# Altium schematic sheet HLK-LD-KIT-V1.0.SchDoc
size A4
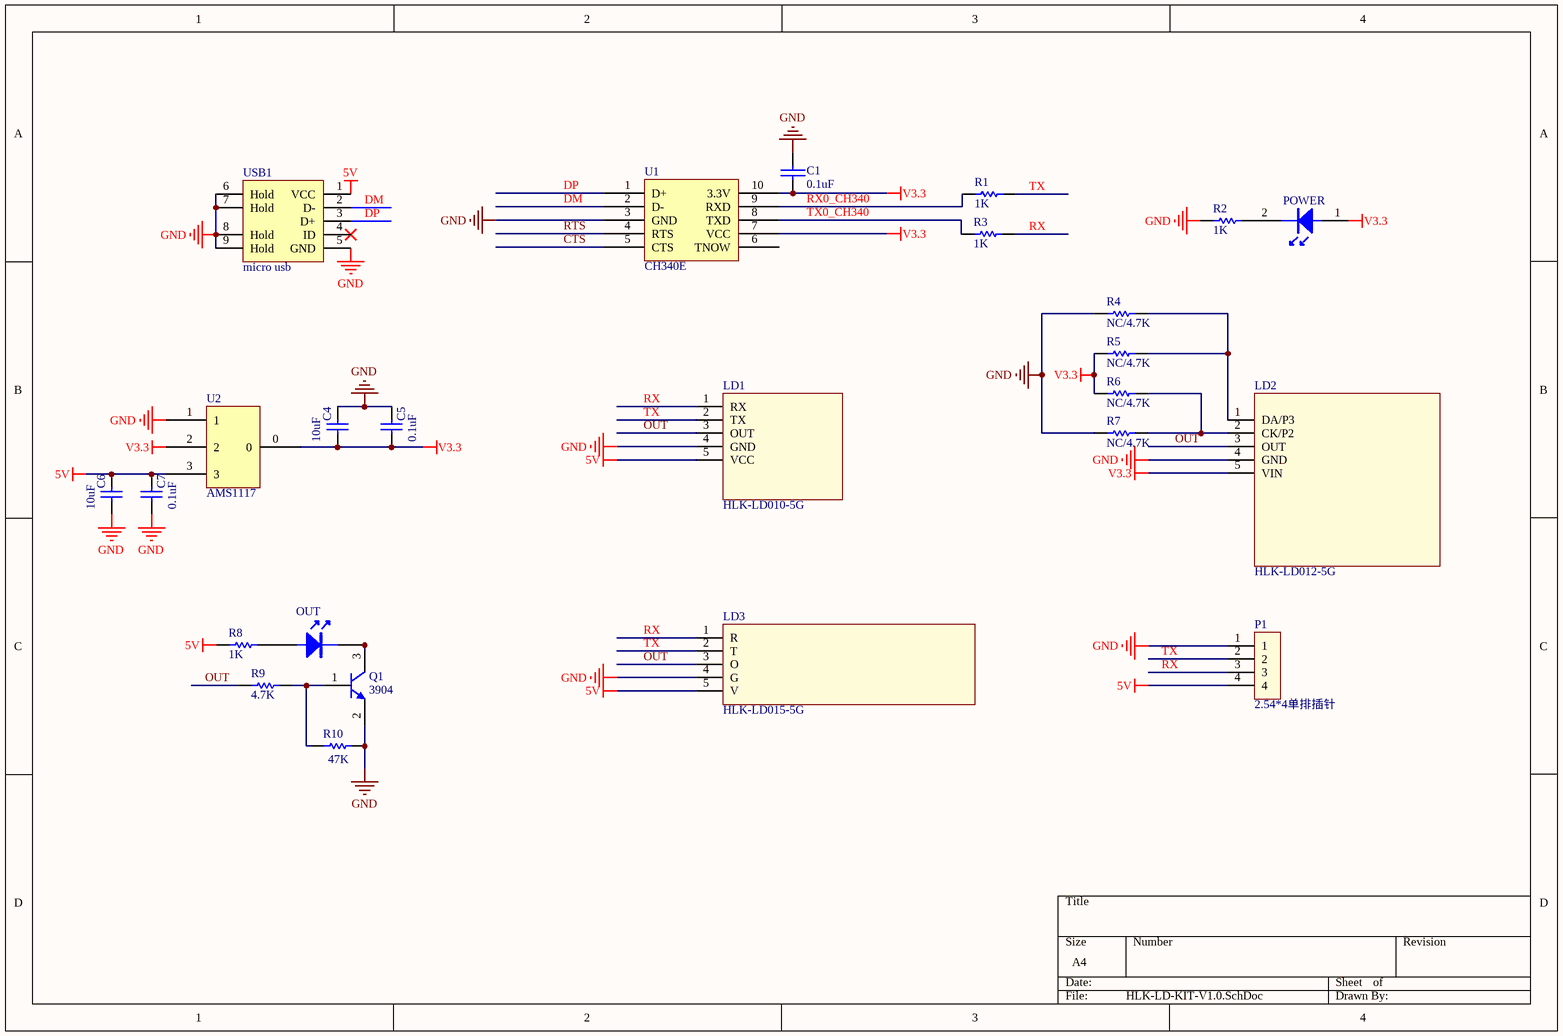
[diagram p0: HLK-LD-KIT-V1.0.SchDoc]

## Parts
C1  0.1uF  [0603]
C4  10uF  [0603]
C5  0.1uF  [0603]
C6  10uF  [0603]
C7  0.1uF  [0603]
LD1  HLK-LD010-5G  [HLK-LD010-5G]
LD2  HLK-LD012-5G  [HLK-LD012-5G]
LD3  HLK-LD015-5G  [HLK-LD015-5G]
OUT  (no value)  [0603LED]
P1  2.54*4单排插针  [SIP_4P_2.54]
POWER  LED  [0603LED]  (value not drawn)
Q1  3904  [SOT-23]
R1  1K  [0603]
R2  1K  [0603]
R3  1K  [0603]
R4  NC/4.7K  [0603]
R5  NC/4.7K  [0603]
R6  NC/4.7K  [0603]
R7  NC/4.7K  [0603]
R8  1K  [0603]
R9  4.7K  [0603]
R10  47K  [0603]
U1  CH340E  [MSOP-10]
U2  AMS1117  [1117]
USB1  micro usb  [USB-MICRO_D]

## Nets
5V: C6.1 C7.1 LD1.5(VCC) LD3.5(V) P1.4 R8.1 U2.3 USB1.1(VCC)
GND: C1.1 C4.1 C5.1 C6.2 C7.2 LD1.4(GND) LD2.4(GND) LD3.4(G) P1.1 Q1.2(E) R2.2 R4.2 R7.2 R10.1 U1.3(GND) U2.1 USB1.5(GND) USB1.6(Hold) USB1.7(Hold) USB1.8(Hold) USB1.9(Hold)
V3.3: C1.2 C4.2 C5.2 LD2.5(VIN) POWER.1 R5.2 R6.2 U1.7(VCC) U1.10(3.3V) U2.0 U2.2
CTS: U1.5(CTS)
DM: U1.2(D-) USB1.2(D-)
DP: U1.1(D+) USB1.3(D+)
OUT: LD1.3(OUT) LD2.3(OUT) LD3.3(O) R9.2
RTS: U1.4(RTS)
RX: LD1.1(RX) LD3.1(R) P1.3 R3.1
RX0_CH340: R1.2 U1.9(RXD)
TX: LD1.2(TX) LD3.2(T) P1.2 R1.1
TX0_CH340: R3.2 U1.8(TXD)
NetLD2_1: LD2.1(DA/P3) R4.1 R5.1
NetLD2_2: LD2.2(CK/P2) R6.1 R7.1
NetOUT_1: OUT.1 R8.2
NetOUT_2: OUT.2 Q1.3(C)
NetPOWER_2: POWER.2 R2.1
NetQ1_1: Q1.1(B) R9.1 R10.2

Not connected (* = marked no-connect by the designer): U1 6(TNOW); USB1 4(ID)*

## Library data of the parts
C1 = CAP: Capacitor
C4-C7 = Cap: Capacitor; Value: 100pF
OUT = LED
P1 = 2.54*2插针
Q1 = A09T: NPN General Purpose Amplifier
R1-R10 = Res1: Resistor
U2 = Component_1
USB1 = USB-D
